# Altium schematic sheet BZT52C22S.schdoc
size 127 x 101 mm
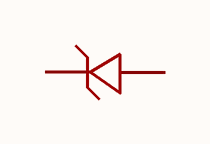
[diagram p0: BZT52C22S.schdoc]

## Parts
D?  bzt52c22s_c22619  [SOD-323_L1.8-W1.3-LS2.5-RD]  (value not drawn)

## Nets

Not connected (* = marked no-connect by the designer): D? 1(K) 2(A)

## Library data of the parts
D? = bzt52c22s_c22619: 二极管配置:1个独立式;稳压值(标称值):22V;稳压值(范围):20.8V~23.3V;耗散功率(Pd):200mW;; Manufacturer: CJ(江苏长电/长晶); AddInBom: yes; ModelId: db63db13d9e342eb939127d413d6200b; ModelTransform: 104.3305,51.181,0,0,0,0,0,-0.004,0; Diode Configuration: 1个独立式; Zener Voltage(Nom): 22V; Reverse Leakage Current (Ir): 100nA; Pd - Power Dissipation: 200mW; Impedance(Zzt): 55Ω; Impedance(Zzk): 250Ω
